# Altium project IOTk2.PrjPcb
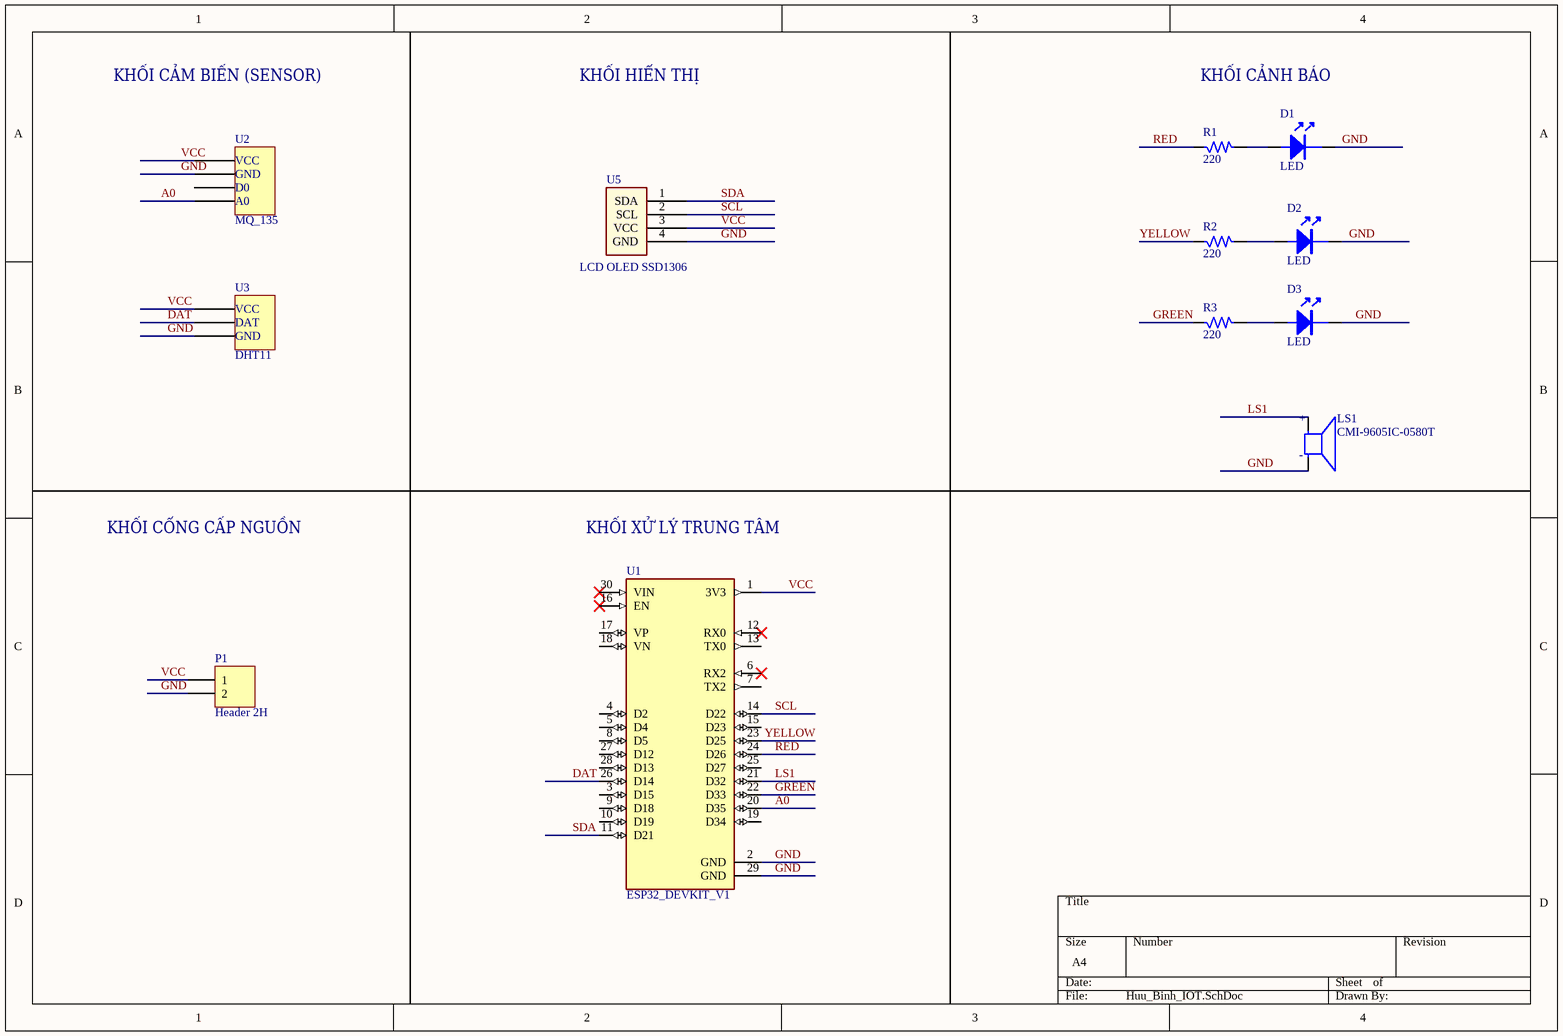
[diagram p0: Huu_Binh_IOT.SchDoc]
1 sheet, 12 parts. Net scope: global (net labels, ports and power ports of the same name join across sheets).
Board file: IoTs_PCB.PcbDoc

## Sheet Huu_Binh_IOT.SchDoc
size A4; DrawnBy: NGUYỄN HỮU BÌNH; SheetNumber: 1; SheetTotal: 1

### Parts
D1  LED  [CAP10UF]
D2  LED  [CAP10UF]
D3  LED  [CAP10UF]
LS1  CMI-9605IC-0580T  [CUI_CMI-9605IC-0580T]
P1  Header 2H  [HDR1X2H]
R1  220  [R1/6W]
R2  220  [R1/6W]
R3  220  [R1/6W]
U1  ESP32_DEVKIT_V1  [ESP32_DEVKIT_V1]
U2  MQ_135  [MQ_135]
U3  DHT11  [DHT11]
U5  LCD OLED SSD1306  [LCD SH1106]

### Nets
A0: U1.20(D35) U2.4
DAT: U1.26(D14) U3.2
GND: D1.2 D2.2 D3.2 LS1.N P1.2 U1.2(GND) U1.29(GND) U2.2 U3.3 U5.4(GND)
GREEN: R3.1 U1.22(D33)
LS1: LS1.P U1.21(D32)
RED: R1.1 U1.24(D26)
SCL: U1.14(D22) U5.2(SCL)
SDA: U1.11(D21) U5.1(SDA)
VCC: P1.1 U1.1(3V3) U2.1 U3.1 U5.3(VCC)
YELLOW: R2.1 U1.23(D25)
NetD1_1: D1.1 R1.2
NetD2_1: D2.1 R2.2
NetD3_1: D3.1 R3.2

Not connected (* = marked no-connect by the designer): U1 3(D15) 4(D2) 5(D4) 6(RX2)* 7(TX2) 8(D5) 9(D18) 10(D19) 12(RX0)* 13(TX0) 15(D23) 16(EN)* 17(VP) 18(VN) 19(D34) 25(D27) 27(D12) 28(D13) 30(VIN)*; U2 3

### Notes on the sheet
- KHỐI CẢM BIẾN (SENSOR)
- KHỐI HIỂN THỊ
- KHỐI CẢNH BÁO
- KHỐI CỔNG CẤP NGUỒN
- KHỐI XỬ LÝ TRUNG TÂM

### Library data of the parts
LS1 = CMI-9605IC-0580T: 9.6 mm, 5 Vdc, 80 dB, Through Hole, Driving Circuit, Magnetic Audio Indicator Buzzer; MF: Same Sky
P1 = Header 2H: Header, 2-Pin, Right Angle
R1-R3 = Res: Resistor 1/4W; Value: R1/4W - 1K
U5 = LCD SH1106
